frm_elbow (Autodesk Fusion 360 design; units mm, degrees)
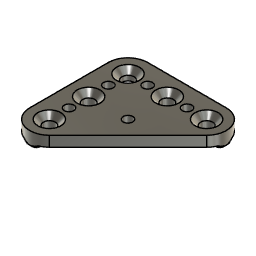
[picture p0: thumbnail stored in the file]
sketch "Sketch1" plane through (0, 0, 0) normal (0, 0, 1) x axis (1, 0, 0)
  line L1 (0, -36) -> (0, 0)
  line L2 (36, 0) -> (0, 0)
  line L3 (-9, -45) -> (-9, 9)
  line L4 (3.7279, -45) -> (-9, -45)
  line L5 (45, 9) -> (45, -3.7279)
  line L6 (-9, 9) -> (45, 9)
  line L7 (10, 10) -> (-10, 10)
  line L8 (10, -10) -> (10, 10)
  line L9 (-10, -10) -> (10, -10)
  line L10 (-10, 10) -> (-10, -10)
  line L11 (-9, 9) -> (0, 0)
  line L12 (25.0711, -10.9289) -> (10.9289, -25.0711)
  line L13 (31.435, -17.2929) -> (25.0711, -10.9289)
  line L14 (17.2929, -31.435) -> (10.9289, -25.0711)
  line L15 (0, 0) -> (18, -18)
  line L16 (10, -38.7279) -> (10, -10)
  line L17 (38.7279, -10) -> (10, -10)
  line L18 (45, -3.7279) -> (3.7279, -45)
  line L19 (12, 3) -> (45, 3)
  line L20 (-3, -45) -> (-3, -12)
  line L21 (12, -3) -> (45, -3)
  line L22 (3, -45) -> (3, -12)
  line L23 (-3, -12) -> (3, -12)
  line L24 (12, 3) -> (12, -3)
  circle C1 centre (0, 0) radius 2.75
  circle C2 centre (18, 0) radius 2.75
  circle C3 centre (36, 0) radius 2.75
  circle C4 centre (0, -18) radius 2.75
  circle C5 centre (0, -36) radius 2.75
  circle C6 centre (0, 0) radius 5
  circle C7 centre (18, 0) radius 5
  circle C8 centre (36, 0) radius 5
  circle C9 centre (0, -18) radius 5
  circle C10 centre (0, -36) radius 5
  circle C11 centre (27, 0) radius 2.2
  circle C12 centre (27, 0) radius 2.5
  circle C13 centre (9, 0) radius 2.2
  circle C14 centre (9, 0) radius 2.5
  circle C15 centre (0, -9) radius 2.2
  circle C16 centre (0, -27) radius 2.2
  circle C17 centre (18, -18) radius 2.2
  point P1 (0, 0)
  point P2 (0, 0)
  point P7 (0, 0)
  point P6 (0, -36)
  point P8 (0, -36)
  point P9 (0, 0)
  point P4 (36, 0)
  point P10 (36, 0)
  point P5 (0, -18)
  point P3 (18, 0)
  point P11 (-9, 9)
  point P16 (-9, 9)
  point P22 (10, 0)
  point P23 (0, -10)
  point P24 (18, 0)
  point P25 (36, 0)
  point P26 (0, -18)
  point P27 (0, -36)
  point P28 (27, 0)
  point P30 (9, 0)
  point P32 (0, 0)
  point P39 (18, -18)
  point P40 (0, 0)
  point P43 (18, -18)
  point P42 (38.7279, -10)
  point P38 (17.2929, -31.435)
  point P41 (10, -38.7279)
  point P37 (31.435, -17.2929)
  point P44 (45, 3)
  point P46 (-3, -45)
  point P47 (45, -3)
  point P49 (3, -45)
  point P18 (-10, 10)
  point P19 (10, 10)
  point P21 (-10, -10)
  point P17 (0, 0)
  point P31 (9, 0)
  point P29 (27, 0)
  point P36 (25.0711, -10.9289)
  coincident P1 P2
  coincident P2 P7
  coincident P6 P8
  coincident P1 P9
  horizontal L2
  coincident P4 P10
  equal L1 L2
  coincident P5 L1
  coincident P3 L2
  equal C2 C3
  equal C2 C4
  equal C4 C5
  equal C1 C5
  vertical L3
  perpendicular L3 L4
  parallel L3 L5
  perpendicular L5 L6
  coincident P11 P16
  concentric C1 C6
  horizontal L7
  vertical L8
  horizontal L9
  vertical L10
  midpoint L8 P22
  midpoint L9 P23
  coincident L1 P23
  coincident L2 P22
  vertical L1
  equal C8 C9
  equal C7 C9
  equal C7 C10
  equal C6 C7
  coincident P3 P24
  coincident P4 P25
  coincident P5 P26
  coincident P6 P27
  coincident L2 P28
  concentric C11 C12
  equal L3 L6
  coincident L2 P30
  concentric C13 C14
  equal C12 C14
  equal C11 C13
  coincident P1 P32
  symmetric C11 L11 C16
  symmetric C13 L11 C15
  perpendicular L12 L13
  perpendicular L12 L14
  midpoint L12 P39
  coincident P2 P40
  parallel L11 L15
  perpendicular L12 L15
  equal L7 L12
  perpendicular L4 L16
  perpendicular L16 L17
  coincident L15 P43
  equal C13 C17
  coincident P42 L18
  coincident P38 L18
  coincident P41 L18
  coincident P37 L18
  coincident L5 P44
  perpendicular L5 L19
  coincident L4 P46
  perpendicular L4 L20
  coincident L5 P47
  perpendicular L5 L21
  perpendicular L9 L22
  coincident L4 P49
  horizontal L23
  vertical L24
  dimension "d1" diameter C1 = 5.5
  dimension "d2" distance P2 L6 = 9 (= "d3")
  dimension "d3" distance P2 L3 = 9
  dimension "d4" diameter C6 = 10
  dimension "d5" distance P18 P19 = 20
  dimension "d6" distance P18 P21 = 20
  dimension "d7" distance P3 P17 = 18
  dimension "d8" distance P5 P17 = 18 (= "d7")
  dimension "d9" distance P3 P4 = 18 (= "d7")
  dimension "d12" distance P3 L8 = 8
  dimension "d13" distance L5 P18 = 55
  dimension "d16" diameter C13 = 4.4
  dimension "d17" diameter C14 = 5
  dimension "d18" distance P17 P31 = 9
  dimension "d19" distance P29 P31 = 18 (= "d7")
  dimension "d27" distance P36 P37 = 9
  dimension "d28" distance P17 P43 = 18
  dimension "d29" angle L5 L18 = 45
  dimension "d30" distance P4 L18 = 9 (= "d18")
  dimension "d32" distance P25 L19 = 3 (= "( 6 / 2 ) * 1 mm")
  dimension "d33" distance P27 L20 = 3 (= "d32")
  dimension "d34" distance P27 L22 = 3 (= "d33")
  dimension "d35" distance P4 L21 = 3 (= "d32")
  dimension "d43" distance P19 L24 = 2
  dimension "d44" distance P21 L23 = 2 (= "d43")
extrude "Extrude1" new body sketch "Sketch1" profile of C1 C2 C3 C4 C5 L3 L4 L5 L6 C11 C13 C15 C16 C17 along normal blind 4.7498
chamfer "Chamfer1" distance 2.5
extrude "Extrude3" add sketch "Sketch1" profile of C2 C3 C4 C5 L4 L5 C11 C16 L19 L20 L21 L22 L23 L24 against normal blind 1.5
fillet "Fillet1" radius 9
fillet "Fillet3" ChordLen 3
chamfer "Chamfer5" distance 0.75
chamfer "Chamfer6" distance 0.5
named bodies: "frm_elbow"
